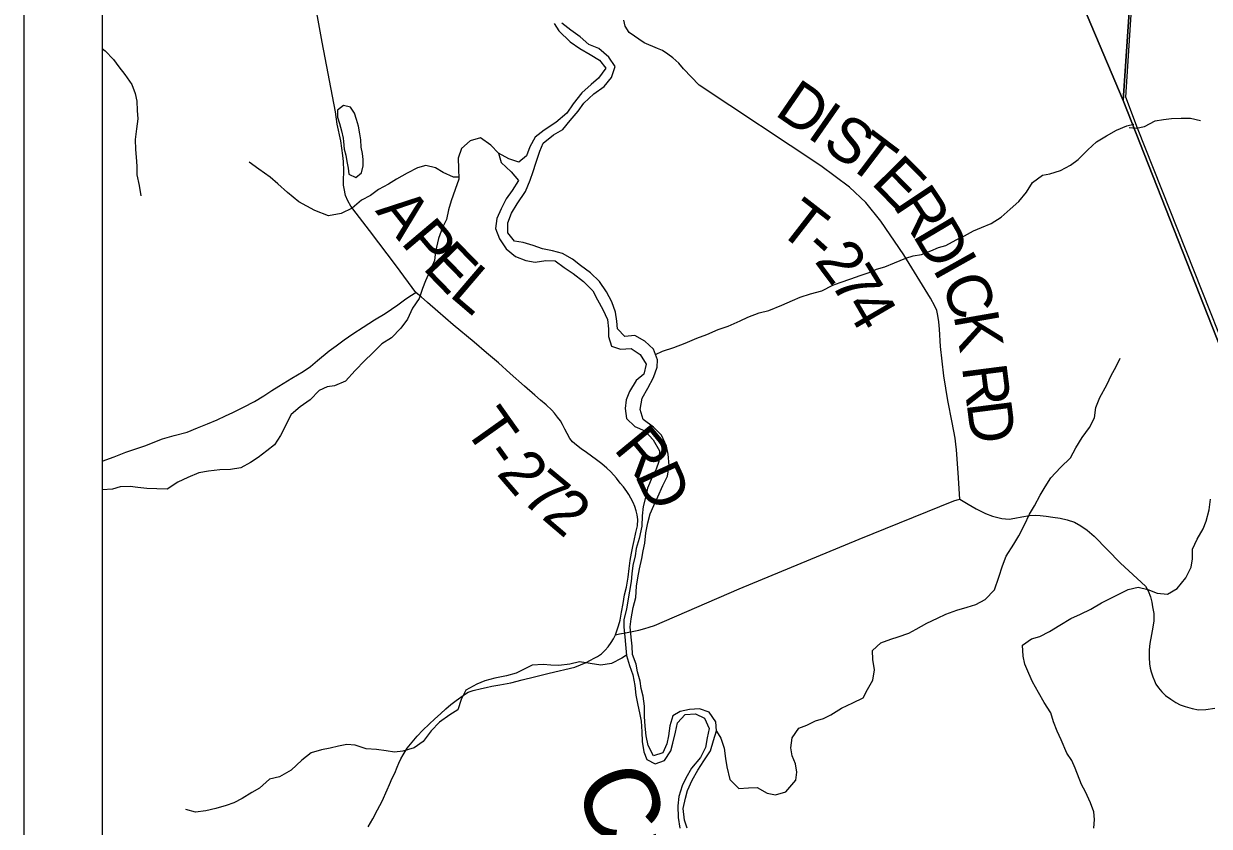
# Model space of a CAD drawing. Extents: x 0 to 34, y 0 to 22.
# Drawn here: x 2 to 3.511, y 17.341 to 18.363 of the extents above; entities that cross this region are included whole.
import ezdxf

# ---------------------------------------------------------------- set-up
doc = ezdxf.new("R2010")
doc.units = 0
for name, color, linetype in [('GM_X_Minor_Lake', 7, 'Continuous'), ('GM_X_Minor_River', 7, 'Continuous'), ('GM_X_Minor_River_Text', 7, 'Continuous'), ('GM_X_Section', 7, 'Continuous'), ('GM_X_Township_Road', 7, 'Continuous'), ('GM_X_Township_Road_Text', 7, 'Continuous'), ('GM_X_Unincorporated', 7, 'Continuous'), ('SH_Cut_Line', 7, 'Continuous'), ('SH_Data', 7, 'Continuous')]:
    doc.layers.add(name, color=color, linetype=linetype)

msp = doc.modelspace()

# ---------------------------------------------------------------- linework, layer by layer
at = {"layer": 'GM_X_Minor_Lake'}
for points in [[(2.4189, 18.2533), (2.4164, 18.2568), (2.4073, 18.2592), (2.3997, 18.2531), (2.3997, 18.2444), (2.4026, 18.2361), (2.4048, 18.227), (2.4071, 18.2175), (2.4077, 18.2131)], [(2.4077, 18.2131), (2.4085, 18.2034), (2.4103, 18.1958), (2.4118, 18.1879), (2.4133, 18.1791), (2.4143, 18.1716), (2.423, 18.1673), (2.4306, 18.1734), (2.4326, 18.1824), (2.4326, 18.1904), (2.4319, 18.198), (2.4301, 18.206), (2.4294, 18.2154), (2.4283, 18.223), (2.4268, 18.2329), (2.4242, 18.2412), (2.4216, 18.2492), (2.4189, 18.2533)]]:
    msp.add_lwpolyline(points, dxfattribs=at)
at = {"layer": 'GM_X_Minor_River'}
for points in [[(2.6758, 18.3636), (2.6818, 18.3541), (2.6964, 18.3403), (2.7085, 18.3315), (2.7217, 18.3238), (2.7337, 18.3169), (2.7416, 18.3066), (2.7324, 18.2938), (2.7229, 18.2859), (2.7111, 18.2754), (2.7, 18.2611), (2.6919, 18.2494), (2.6782, 18.2374), (2.6634, 18.2276), (2.6516, 18.2186), (2.645, 18.2065), (2.6408, 18.1948), (2.6309, 18.1869), (2.618, 18.1912), (2.6052, 18.1985), (2.6082, 18.1863), (2.6213, 18.1745), (2.6303, 18.1634), (2.6226, 18.151), (2.6146, 18.1404), (2.6085, 18.1276), (2.6027, 18.1151), (2.6011, 18.1026), (2.6063, 18.0893), (2.6149, 18.0767), (2.6265, 18.0668), (2.6397, 18.0617), (2.6518, 18.0597), (2.6655, 18.0619), (2.6772, 18.0614), (2.6885, 18.0526), (2.7002, 18.0453), (2.7133, 18.035), (2.725, 18.0231), (2.7313, 18.0117), (2.738, 17.9995), (2.744, 17.9866), (2.745, 17.9748), (2.7453, 17.965), (2.749, 17.9524), (2.7604, 17.9489), (2.774, 17.9496), (2.7857, 17.9419), (2.7931, 17.9297), (2.79, 17.9168), (2.7805, 17.909)], [(2.7855, 17.8721), (2.7882, 17.8865), (2.7955, 17.899), (2.8025, 17.9126), (2.8071, 17.9258), (2.8076, 17.9353), (2.8027, 17.9486), (2.7915, 17.9589), (2.7787, 17.9662), (2.7658, 17.9648), (2.7568, 17.9747), (2.7557, 17.9846), (2.7543, 17.996), (2.7495, 18.0089), (2.7428, 18.0219), (2.7338, 18.0348), (2.7221, 18.0459), (2.7097, 18.0555), (2.6992, 18.0635), (2.6867, 18.0705), (2.6739, 18.074), (2.6611, 18.0767), (2.6493, 18.0806), (2.6365, 18.0845), (2.6252, 18.0861), (2.6169, 18.0968), (2.617, 18.1097), (2.6217, 18.1218), (2.6289, 18.1338), (2.6393, 18.1497), (2.6455, 18.164), (2.6493, 18.175), (2.6524, 18.1856), (2.6575, 18.2007), (2.6621, 18.2109), (2.6751, 18.2218), (2.6869, 18.2286), (2.6964, 18.2399), (2.7067, 18.2519), (2.7136, 18.2621), (2.7266, 18.2741), (2.7395, 18.2831), (2.7491, 18.2948), (2.7537, 18.3088), (2.7455, 18.3206), (2.7327, 18.3317), (2.7203, 18.3367), (2.709, 18.3467), (2.6973, 18.3551), (2.6856, 18.3639)], [(2.1, 18.3317), (2.1036, 18.3287), (2.1145, 18.3176), (2.1212, 18.3081), (2.1287, 18.2985), (2.1377, 18.286), (2.1421, 18.2742), (2.144, 18.2647), (2.1446, 18.2525), (2.1453, 18.2419), (2.1437, 18.2294), (2.1421, 18.2158), (2.1423, 18.2029), (2.1434, 18.1934), (2.1441, 18.1816), (2.144, 18.1706), (2.1473, 18.157), (2.1491, 18.1441)], [(2.8051, 17.9421), (2.8141, 17.9462), (2.8285, 17.951), (2.8429, 17.9566), (2.8577, 17.9629), (2.8706, 17.9674), (2.8851, 17.9737), (2.8976, 17.9782), (2.9128, 17.9849), (2.9227, 17.9897), (2.9371, 17.9949), (2.9496, 17.9982), (2.9659, 18.0049), (2.9796, 18.0109), (2.9895, 18.015), (3.0024, 18.0191), (3.0172, 18.0231), (3.0309, 18.0302), (3.0404, 18.0335), (3.054, 18.0384), (3.0658, 18.0424), (3.0772, 18.0465), (3.0867, 18.0506), (3.0973, 18.0536), (3.1095, 18.0588), (3.1239, 18.0647), (3.1334, 18.0677), (3.144, 18.0695), (3.1561, 18.074), (3.1656, 18.0781), (3.1751, 18.081), (3.188, 18.0881), (3.1987, 18.0933), (3.2101, 18.0993), (3.2203, 18.1038), (3.2329, 18.1086), (3.2454, 18.1169), (3.2569, 18.127), (3.2679, 18.1368), (3.2778, 18.1485), (3.2855, 18.1609), (3.2981, 18.1703), (3.3076, 18.1721), (3.3212, 18.1762), (3.3338, 18.1829), (3.3437, 18.1904), (3.3559, 18.2024), (3.3669, 18.213), (3.3799, 18.2205), (3.3924, 18.2276), (3.4057, 18.2331), (3.4144, 18.2351)], [(3.4086, 18.231), (3.4181, 18.23), (3.4283, 18.2324), (3.4419, 18.2397), (3.4525, 18.2413), (3.4627, 18.2426), (3.4749, 18.2431), (3.4867, 18.2428), (3.4996, 18.2399)], [(2.6052, 18.1985), (2.5951, 18.2084), (2.5819, 18.218), (2.569, 18.2139), (2.558, 18.2045), (2.5537, 18.1921), (2.554, 18.1788), (2.5543, 18.1651), (2.5496, 18.1523), (2.5446, 18.1375), (2.5415, 18.1262), (2.5387, 18.1141), (2.5337, 18.1035), (2.5287, 18.0899), (2.5248, 18.0732), (2.5235, 18.0619), (2.5174, 18.0483), (2.512, 18.0358), (2.5081, 18.026), (2.5038, 18.0135), (2.4954, 18.0011), (2.4889, 17.9871), (2.4805, 17.9754), (2.4686, 17.9633), (2.4565, 17.9555), (2.4442, 17.9431), (2.4347, 17.9344), (2.4225, 17.9216), (2.4099, 17.9081), (2.3962, 17.9021), (2.3868, 17.901), (2.3765, 17.8962), (2.365, 17.8842), (2.3521, 17.8752), (2.3407, 17.8654), (2.3272, 17.839), (2.3196, 17.8269), (2.3097, 17.8194), (2.2986, 17.8107), (2.2891, 17.8044), (2.2766, 17.7976), (2.2633, 17.7955), (2.2497, 17.7952), (2.2353, 17.7934), (2.2231, 17.7912), (2.2091, 17.7853), (2.1962, 17.7793), (2.1828, 17.7707), (2.1696, 17.7708), (2.1567, 17.7713), (2.1454, 17.7725), (2.1356, 17.7737), (2.1231, 17.7734), (2.1132, 17.7705), (2.1, 17.7695)], [(2.5542, 18.1679), (2.5478, 18.1678), (2.5346, 18.1736), (2.5248, 18.1798), (2.5124, 18.1825), (2.5018, 18.1796), (2.4888, 18.1729), (2.4751, 18.1654), (2.4649, 18.159), (2.4523, 18.1519), (2.442, 18.1444), (2.4303, 18.1384), (2.4185, 18.1283), (2.4044, 18.1216), (2.3885, 18.1187), (2.3711, 18.1253), (2.3606, 18.131), (2.3504, 18.1364), (2.3361, 18.1483), (2.3237, 18.1594), (2.3139, 18.1678), (2.2996, 18.1778), (2.2872, 18.187)], [(2.8828, 17.4622), (2.8885, 17.4535), (2.8926, 17.4406), (2.8944, 17.4277), (2.8958, 17.417), (2.8999, 17.4007), (2.9111, 17.3892), (2.9236, 17.3903), (2.9346, 17.3906), (2.9474, 17.3836), (2.958, 17.3813), (2.9713, 17.385), (2.9839, 17.4), (2.9851, 17.4103), (2.9833, 17.4209), (2.9792, 17.4308), (2.9774, 17.441), (2.979, 17.4539), (2.9878, 17.466), (2.9977, 17.4701), (3.0091, 17.4753), (3.019, 17.4786), (3.0285, 17.4831), (3.0421, 17.4917), (3.0566, 17.4984), (3.0695, 17.5048), (3.0753, 17.5153), (3.0822, 17.5274), (3.0842, 17.5403), (3.082, 17.5536), (3.0817, 17.565), (3.0924, 17.5747), (3.1049, 17.5796), (3.1144, 17.5825), (3.1277, 17.587), (3.1372, 17.5922), (3.1509, 17.5997), (3.1642, 17.6064), (3.1752, 17.6112), (3.1892, 17.6164), (3.2021, 17.6201), (3.2131, 17.6238), (3.2253, 17.6302), (3.2371, 17.6422), (3.2426, 17.6585), (3.2472, 17.6729), (3.2519, 17.6853), (3.2618, 17.7004), (3.268, 17.711), (3.2753, 17.7253), (3.2818, 17.7386), (3.2879, 17.7491), (3.2952, 17.7627), (3.3014, 17.7733), (3.3087, 17.785), (3.3213, 17.7982), (3.3338, 17.8106), (3.3408, 17.823), (3.3488, 17.8362), (3.358, 17.8491), (3.3645, 17.8615), (3.3661, 17.8744), (3.3712, 17.8872), (3.38, 17.9035), (3.3862, 17.9159), (3.3915, 17.9258), (3.3973, 17.9375)], [(2.7805, 17.909), (2.772, 17.895), (2.7678, 17.8844), (2.7662, 17.8734), (2.768, 17.8605), (2.7789, 17.8502), (2.7913, 17.8448), (2.8022, 17.8333), (2.81, 17.8192), (2.8092, 17.8056), (2.8061, 17.7958), (2.8007, 17.7859), (2.7949, 17.7716), (2.7926, 17.7617), (2.7894, 17.7485), (2.7882, 17.7364), (2.7877, 17.7235), (2.7842, 17.7076), (2.7803, 17.6951), (2.7791, 17.6856), (2.776, 17.6731), (2.7751, 17.6625), (2.7739, 17.6531), (2.7719, 17.6406), (2.7699, 17.6285), (2.7683, 17.6179), (2.7648, 17.6046), (2.7648, 17.5948), (2.7658, 17.5826), (2.7669, 17.5727), (2.7683, 17.5587), (2.7719, 17.5458), (2.776, 17.534), (2.7789, 17.5203), (2.78, 17.5082), (2.7825, 17.4953), (2.7847, 17.4858), (2.7869, 17.4751), (2.7875, 17.4615), (2.7882, 17.449), (2.7904, 17.4361), (2.7941, 17.4262), (2.8046, 17.4208), (2.8164, 17.4249), (2.8248, 17.4373), (2.8272, 17.4471), (2.8307, 17.4611), (2.8331, 17.4729), (2.843, 17.4834), (2.8562, 17.4845), (2.8676, 17.4791), (2.8735, 17.4657), (2.8711, 17.454), (2.8688, 17.4415), (2.8622, 17.429), (2.8508, 17.4151), (2.8435, 17.4027), (2.8392, 17.3928), (2.8346, 17.3792), (2.8334, 17.3671), (2.834, 17.3523), (2.8362, 17.339)], [(2.8453, 17.3389), (2.8419, 17.3492), (2.8405, 17.364), (2.8433, 17.3769), (2.846, 17.3867), (2.8518, 17.3999), (2.8591, 17.4128), (2.8667, 17.4245), (2.8752, 17.4373), (2.8791, 17.4505), (2.8829, 17.4626), (2.8819, 17.4744), (2.8733, 17.4866), (2.8612, 17.4909), (2.8483, 17.4898), (2.8366, 17.4876), (2.8271, 17.482), (2.8232, 17.4692), (2.8216, 17.4563), (2.8196, 17.4464), (2.8146, 17.4347), (2.8024, 17.431), (2.7957, 17.444), (2.7932, 17.4565), (2.7921, 17.4687), (2.7911, 17.4812), (2.7912, 17.4941), (2.7894, 17.507), (2.7868, 17.5165), (2.7854, 17.526), (2.7821, 17.5381), (2.7803, 17.5476), (2.7758, 17.5598), (2.7752, 17.5704), (2.7741, 17.5822), (2.7727, 17.5954), (2.7739, 17.6053), (2.7767, 17.6197), (2.7798, 17.6325), (2.7807, 17.6469), (2.7827, 17.6575), (2.7846, 17.6689), (2.7878, 17.6822), (2.7894, 17.692), (2.7913, 17.7018), (2.7926, 17.7151), (2.7953, 17.7276), (2.7984, 17.7389), (2.8031, 17.7495), (2.8081, 17.7609), (2.8146, 17.7752), (2.8204, 17.7869), (2.8224, 17.8006), (2.8214, 17.815), (2.8192, 17.8252), (2.8129, 17.8393), (2.8023, 17.8496), (2.7895, 17.8592), (2.7855, 17.8721)], [(3.3638, 17.339), (3.3643, 17.35), (3.3636, 17.3595), (3.3595, 17.3713), (3.3528, 17.385), (3.348, 17.3945), (3.3398, 17.4154), (3.3354, 17.4249), (3.329, 17.4345), (3.3219, 17.4512), (3.3167, 17.4623), (3.3123, 17.4744), (3.309, 17.4858), (3.3004, 17.4988), (3.2929, 17.5114), (3.2854, 17.5251), (3.2806, 17.5357), (3.2758, 17.5475), (3.2736, 17.5578), (3.2725, 17.5718), (3.2843, 17.58), (3.2946, 17.583), (3.3071, 17.5893), (3.3204, 17.5972), (3.3341, 17.6058), (3.3467, 17.6114), (3.3596, 17.6178), (3.3733, 17.6256), (3.387, 17.6327), (3.4075, 17.6428), (3.42, 17.6457), (3.4325, 17.6426), (3.4445, 17.6379), (3.4574, 17.6367), (3.4696, 17.6442), (3.481, 17.6574), (3.4876, 17.6713), (3.4892, 17.6819), (3.4893, 17.6941), (3.4954, 17.7069), (3.5031, 17.7198), (3.5066, 17.7296), (3.5105, 17.744), (3.5121, 17.7576)], [(2.7682, 17.5591), (2.7622, 17.5553), (2.7492, 17.5486), (2.7352, 17.5464), (2.722, 17.5484), (2.7084, 17.5505), (2.6959, 17.5475), (2.6819, 17.5461), (2.6716, 17.5462), (2.6618, 17.5474), (2.6478, 17.5464), (2.6379, 17.5411), (2.6273, 17.5363), (2.6151, 17.533), (2.6003, 17.5297), (2.5874, 17.5264), (2.5772, 17.5223), (2.5635, 17.5144), (2.5574, 17.5027), (2.5531, 17.4895), (2.5428, 17.4831), (2.5299, 17.4737), (2.5192, 17.4628), (2.5089, 17.4493), (2.4974, 17.441), (2.483, 17.437), (2.4724, 17.4355), (2.4618, 17.4371), (2.4497, 17.4391), (2.4365, 17.44), (2.4225, 17.4446), (2.4119, 17.4455), (2.4013, 17.4433), (2.3903, 17.4407), (2.3793, 17.4385), (2.3664, 17.4348), (2.3542, 17.4255), (2.3409, 17.4127), (2.3261, 17.4044), (2.3132, 17.4011), (2.3006, 17.3899), (2.2907, 17.3842), (2.2785, 17.3768), (2.2679, 17.3712), (2.258, 17.3678), (2.2447, 17.3638), (2.2322, 17.3608), (2.219, 17.3594), (2.2065, 17.3625)]]:
    msp.add_lwpolyline(points, dxfattribs=at)
at = {"layer": 'GM_X_Section'}
msp.add_lwpolyline([(3.4282, 18.6383), (4.4314, 18.5943), (4.383, 17.5655), (3.6608, 17.6237), (3.615, 17.7371), (3.4191, 18.2301), (3.4042, 18.2698)], close=True, dxfattribs=at)
at = {"layer": 'GM_X_Township_Road'}
for points in [[(2.7539, 17.5849), (2.7579, 17.5964), (2.76, 17.6038), (2.7619, 17.6137), (2.7638, 17.625), (2.7655, 17.636), (2.768, 17.6459), (2.7701, 17.6585), (2.7716, 17.6693), (2.7728, 17.6796), (2.7745, 17.689), (2.776, 17.6975), (2.7779, 17.7053), (2.7802, 17.7154), (2.7821, 17.724), (2.7825, 17.7318), (2.7815, 17.7377), (2.7804, 17.743), (2.7789, 17.7486), (2.7768, 17.7537), (2.7737, 17.7592), (2.7711, 17.7636), (2.7684, 17.7674), (2.7642, 17.7735), (2.7602, 17.7783), (2.7555, 17.7845), (2.748, 17.7924), (2.7429, 17.7973), (2.7368, 17.8028), (2.7297, 17.808), (2.7237, 17.8127), (2.7172, 17.8173), (2.7103, 17.8217), (2.7044, 17.8264), (2.6995, 17.8308), (2.6958, 17.8352), (2.6924, 17.8413), (2.6896, 17.847), (2.6867, 17.8529), (2.684, 17.8575), (2.6802, 17.8624), (2.6764, 17.8672), (2.6728, 17.871), (2.6656, 17.8779), (2.6585, 17.8839), (2.6515, 17.8902), (2.638, 17.9018), (2.6197, 17.9178), (2.6048, 17.9312), (2.5896, 17.9443), (2.5742, 17.9578), (2.5473, 17.9797), (2.5277, 17.9967), (2.5144, 18.0083), (2.5066, 18.0155), (2.4995, 18.0211), (2.4751, 18.0546), (2.4407, 18.0998), (2.4236, 18.1218), (2.4169, 18.131), (2.4129, 18.1375), (2.4102, 18.1444), (2.4083, 18.1534), (2.4077, 18.1578), (2.4077, 18.1633), (2.4079, 18.176), (2.4077, 18.1876), (2.4066, 18.1954), (2.4039, 18.2139), (2.3995, 18.2353), (2.3972, 18.251), (2.3804, 18.3396), (2.3737, 18.377)], [(3.1928, 17.7577), (3.1907, 17.7912), (3.1886, 17.8205), (3.1876, 17.8276), (3.1868, 17.8356), (3.183, 17.8555), (3.1775, 17.8835), (3.1725, 17.9149), (3.1681, 17.952), (3.1669, 17.9744), (3.1662, 17.9838), (3.165, 17.9918), (3.1637, 17.9979), (3.161, 18.0037), (3.1556, 18.0136), (3.1216, 18.0689), (3.0921, 18.1117), (3.0732, 18.1355), (3.0523, 18.1551), (3.0159, 18.1822), (2.8606, 18.2851), (2.8409, 18.3058), (2.8346, 18.3128), (2.827, 18.3197), (2.8208, 18.3243), (2.8141, 18.3289), (2.8074, 18.3318), (2.7905, 18.339), (2.7716, 18.352), (2.7663, 18.3601), (2.7647, 18.3677)], [(2.1, 17.8061), (2.1152, 17.8116), (2.1301, 17.8177), (2.1545, 17.8257), (2.1769, 17.8344), (2.1918, 17.839), (2.2082, 17.8432), (2.2215, 17.8485), (2.2342, 17.8535), (2.2466, 17.8588), (2.2573, 17.8638), (2.2664, 17.868), (2.2801, 17.8748), (2.2942, 17.882), (2.306, 17.8893), (2.3163, 17.8961), (2.3251, 17.9015), (2.3418, 17.9118), (2.3559, 17.9205), (2.3655, 17.9266), (2.3742, 17.9342), (2.3891, 17.9468), (2.3982, 17.9529), (2.4085, 17.9605), (2.4195, 17.9685), (2.4325, 17.9769), (2.447, 17.986), (2.4607, 17.9944), (2.4767, 18.0054), (2.4854, 18.0115), (2.4919, 18.0161), (2.4995, 18.0211)], [(2.7539, 17.5849), (2.759, 17.5864), (2.767, 17.5877), (2.7753, 17.5891), (2.7837, 17.5908), (2.7915, 17.5929), (2.7971, 17.5946), (2.8036, 17.5969), (2.9118, 17.6434), (3.0647, 17.707), (3.1851, 17.7556), (3.1893, 17.7571), (3.1928, 17.7577)], [(3.1928, 17.7577), (3.2035, 17.7514), (3.2138, 17.7453), (3.2254, 17.7396), (3.2343, 17.7361), (3.2464, 17.7332), (3.2556, 17.7324), (3.263, 17.7334), (3.2718, 17.7351), (3.2818, 17.737), (3.2898, 17.7374), (3.2954, 17.737), (3.303, 17.7363), (3.3115, 17.7349), (3.3206, 17.7334), (3.3298, 17.7313), (3.339, 17.7284), (3.3471, 17.724), (3.3551, 17.7185), (3.3641, 17.7106), (3.3974, 17.6762), (3.4296, 17.6469), (3.433, 17.6409), (3.4359, 17.6333), (3.4376, 17.6268), (3.4384, 17.6206), (3.4399, 17.612), (3.4399, 17.6028), (3.4386, 17.5946), (3.437, 17.5854), (3.4351, 17.5741), (3.434, 17.5659), (3.434, 17.5561), (3.4347, 17.5483), (3.4355, 17.5427), (3.4365, 17.5381), (3.4386, 17.5316), (3.4409, 17.5263), (3.4428, 17.5224), (3.4462, 17.5177), (3.4502, 17.5123), (3.455, 17.5079), (3.4617, 17.5033), (3.4682, 17.4987), (3.4736, 17.4958), (3.4801, 17.4937), (3.4889, 17.4912), (3.4968, 17.4897), (3.5065, 17.4901), (3.5176, 17.4918)], [(2.4388, 17.3405), (2.4447, 17.3506), (2.4508, 17.362), (2.4567, 17.3734), (2.4631, 17.3875), (2.466, 17.3945), (2.4694, 17.4025), (2.4727, 17.409), (2.4757, 17.4164), (2.4778, 17.4214), (2.4805, 17.4271), (2.4835, 17.4324), (2.4887, 17.4406), (2.4948, 17.4482), (2.5014, 17.4559), (2.5085, 17.4637), (2.5167, 17.4711), (2.5237, 17.478), (2.5313, 17.4846), (2.5378, 17.4909), (2.5441, 17.4962), (2.5509, 17.5014), (2.5568, 17.5058), (2.5618, 17.5092), (2.5665, 17.5122), (2.5728, 17.5143), (2.5833, 17.5168), (2.5894, 17.5179), (2.5964, 17.5195), (2.6065, 17.5214), (2.6208, 17.524), (2.6353, 17.5277), (2.6507, 17.5315), (2.6696, 17.5362), (2.7023, 17.544), (2.7094, 17.5467), (2.7168, 17.5499), (2.7223, 17.5528), (2.7269, 17.5553), (2.7313, 17.5576), (2.7362, 17.561), (2.7408, 17.5654), (2.7448, 17.5699), (2.7484, 17.5751), (2.7515, 17.5798), (2.7539, 17.5849)]]:
    msp.add_lwpolyline(points, dxfattribs=at)
at = {"layer": 'GM_X_Unincorporated'}
for points in [[(2.2853, 20.9), (2.1, 20.9), (2.1, 14.1), (2.8399, 14.1), (2.9778, 14.1609), (3.8099, 14.5285), (4.2904, 14.7408), (4.3998, 14.7897), (4.802, 14.9692), (4.4847, 15.685), (4.2937, 16.1161), (4.0882, 16.6114), (3.972, 16.8916), (3.7367, 17.4136), (3.709, 17.484), (3.4011, 18.2653), (3.1249, 18.9173), (3.0781, 19.0279), (2.9956, 19.2227), (2.9553, 19.318), (2.7473, 19.8121), (2.418, 20.5866)], [(6.769, 20.9), (2.2853, 20.9), (2.418, 20.5866), (2.7473, 19.8121), (2.9553, 19.318), (2.9956, 19.2227), (3.0781, 19.0279), (3.1249, 18.9173), (3.4011, 18.2653), (3.4595, 19.1305), (3.4599, 19.1361), (3.5099, 19.8769), (3.5456, 20.4047), (3.5457, 20.4056), (3.5462, 20.4144), (3.5651, 20.6937), (3.8602, 20.6728), (4.3099, 20.6409), (6.6484, 20.4847), (6.6568, 20.5136)]]:
    msp.add_lwpolyline(points, close=True, dxfattribs=at)
msp.add_lwpolyline([(3.5456, 20.4047), (3.5099, 19.8769), (3.4599, 19.1361), (3.4595, 19.1305), (3.4011, 18.2653), (3.709, 17.484)], dxfattribs=at)
at = {"layer": 'SH_Cut_Line'}
for points in [[(4.2937, 16.1161), (4.0882, 16.6114), (3.972, 16.8916), (3.7367, 17.4136), (3.709, 17.484), (3.4011, 18.2653), (3.4595, 19.1305), (3.4599, 19.1361), (3.5099, 19.8769), (3.5456, 20.4047), (3.5457, 20.4056), (3.5462, 20.4144), (3.5651, 20.6937), (3.8602, 20.6728), (4.3099, 20.6409), (6.6484, 20.4847), (6.6568, 20.5136), (6.769, 20.9), (2.1, 20.9), (2.1, 14.1)], [(8.9, 14.1), (8.9, 20.9), (6.769, 20.9), (6.6568, 20.5136), (6.6484, 20.4847), (4.3099, 20.6409), (3.8602, 20.6728), (3.5651, 20.6937), (3.5462, 20.4144), (3.5457, 20.4056), (3.5456, 20.4047), (3.5099, 19.8769), (3.4599, 19.1361), (3.4595, 19.1305), (3.4011, 18.2653), (3.709, 17.484), (3.7367, 17.4136), (3.972, 16.8916), (4.0882, 16.6114), (4.2937, 16.1161)]]:
    msp.add_lwpolyline(points, dxfattribs=at)
at = {"layer": 'SH_Data'}
for p, q in [((2, 21), (2, 14)), ((2.1, 20.9), (2.1, 14.1))]:
    msp.add_line(p, q, dxfattribs=at)

# ---------------------------------------------------------------- texts
at = {"layer": 'GM_X_Minor_River_Text'}
msp.add_text('Creek', height=0.09469, rotation=292.0026, dxfattribs=at).set_placement((2.7004, 17.3972))
at = {"layer": 'GM_X_Township_Road_Text'}
for s, rotation, p in [('D', 325.5249, (2.9554, 18.248)), ('I', 325.1429, (2.9965, 18.2197)), ('S', 324.1964, (3.0154, 18.2066)), ('T', 322.9133, (3.0463, 18.1843)), ('E', 314.6561, (3.0785, 18.1601)), ('R', 303.5905, (3.1066, 18.1321)), ('A', 308.5739, (2.4472, 18.1247)), ('T', 322.1598, (2.9586, 18.0996)), ('P', 310.135, (2.4794, 18.0843)), ('D', 300.6698, (3.132, 18.0939)), ('E', 314.1792, (2.5071, 18.0517)), ('-', 317.9461, (2.9913, 18.0742)), ('2', 306.669, (3.0067, 18.0608)), ('I', 299.254, (3.1573, 18.0512)), ('L', 319.5092, (2.5409, 18.0173)), ('7', 301.6863, (3.0268, 18.0338)), ('C', 292.2138, (3.1679, 18.0325)), ('4', 300.1315, (3.045, 18.0043)), ('K', 279.9585, (3.1847, 17.9924)), ('R', 277.3027, (3.1954, 17.9265)), ('T', 305.3282, (2.5597, 17.8484)), ('D', 277.3017, (3.2014, 17.8802)), ('R', 309.3608, (2.7507, 17.8213)), ('-', 305.4959, (2.5844, 17.8136)), ('2', 310.7142, (2.6015, 17.7901)), ('7', 320.4145, (2.6318, 17.7563)), ('D', 294.5584, (2.7782, 17.7885)), ('2', 319.5548, (2.6586, 17.7341))]:
    msp.add_text(s, height=0.0568, rotation=rotation, dxfattribs=at).set_placement(p)

doc.saveas('drawing.dxf')
